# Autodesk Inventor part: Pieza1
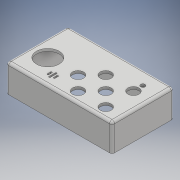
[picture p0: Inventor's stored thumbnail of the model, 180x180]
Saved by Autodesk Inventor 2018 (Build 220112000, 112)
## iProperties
Created: 2020-12
Part Number: Pieza1
Material: Genérico
Document SubType Name: Modeling
Designer: ULISES
Density: 1 g/cm^3
Appearance: Valor por defecto
Author: ULISES
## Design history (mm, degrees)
sketch "Boceto1"
  geometry: L1 (0, 0)-(80, 0); L2 (80, 0)-(80, 45); L3 (80, 45)-(0, 45); L4 (0, 45)-(0, 0); L5 (26, 9.5)-(26, 4.5); L6 (25.4, 9.5)-(25.4, 4.5); L7 (26.6, 4.5)-(26.6, 9.5); L8 (28.5, 8.25)-(28.5, 5.75); L9 (27.9, 8.25)-(27.9, 5.75); L10 (29.1, 5.75)-(29.1, 8.25); L11 (23.5, 8.25)-(23.5, 5.75); L12 (22.9, 5.75)-(22.9, 8.25); L13 (24.1, 8.25)-(24.1, 5.75); C1 r 4.4 at (69, 28); C2 r 4.4 at (69, 6); C3 r 4.4 at (58, 17); C4 r 4.4 at (47, 28); C5 r 4.4 at (47, 6); C6 r 4.4 at (36, 17); C7 r 9 at (12, 17); C8 r 4.4 at (26, 7); C9 r 1.75 at (69, 35.5); A1 r 0.6 centre (26, 9.5) between (26.6, 9.5) and (25.4, 9.5); A2 r 0.6 centre (26, 4.5) between (25.4, 4.5) and (26.6, 4.5); A3 r 0.6 centre (28.5, 8.25) between (29.1, 8.25) and (27.9, 8.25); A4 r 0.6 centre (28.5, 5.75) between (27.9, 5.75) and (29.1, 5.75); A5 r 0.6 centre (23.5, 8.25) between (24.1, 8.25) and (22.9, 8.25); A6 r 0.6 centre (23.5, 5.75) between (22.9, 5.75) and (24.1, 5.75); 3 further points
  constraints: 32 end point, 15 centre point, 12 point on circle, 8 tangent, 7 symmetric about line, 4 horizontal alignment, 4 parallel, 3 vertical alignment, 2 midpoint, 2 vertical, 1 coincident, 1 horizontal, 1 perpendicular, 2 other
  dimensions: "d0" = 7.5 distance of C1.centre C9.centre; "d1" = 22 distance of C2.centre C1.centre (= d2); "d2" = 22 distance of C1.centre C4.centre; "d3" = 11 horizontal distance of C4.centre C3.centre (= 0.5 x d2); "d4" = 11 horizontal distance of C6.centre C4.centre (= d3); "d5" = 11 horizontal distance of C4.centre C3.centre (= d3); "d6" = 24 distance of C6.centre C7.centre; "d7" = 10 horizontal distance of C6.centre C8.centre; "d8" = 10 horizontal distance of C8.centre C6.centre (= d7); "d9" = 17 distance from line of L3 C1.centre; "d10" = 6 distance from line of L1 C2.centre; "d12" = 33 distance from line of L2 C4.centre; "d13" = 12 distance from line of L4 C7.centre; "d14" = 3.5 diameter of C9; "d15" = 8.8 diameter of C1; "d16" = 8.8 diameter of C2; "d17" = 8.8 diameter of C3; "d18" = 8.8 diameter of C5; "d19" = 8.8 diameter of C4; "d20" = 8.8 diameter of C6; "d21" = 8.8 diameter of C8; "d22" = 5 distance of L5.start L5.end; "d23" = 0.6 distance between parallel lines of L7 L5; "d24" = 0.6 distance between parallel lines of L10 L8; "d25" = 2.5 distance between parallel lines of L5 L8; "d26" = 2.5 distance of L8.start L8.end (= 0.5 x d22); "d27" = 1.25 vertical distance of L5.end L8.end (= 0.5 x d26); "d28" = 18 diameter of C7
extrude "Extrusión1" new body sketch "Boceto1" distance "d29" = 2; taper "d30" = 0 deg
sketch "Boceto2"
  geometry: L1 (26.6, 9.5)-(26.6, 4.5) reference; L2 (25.4, 4.5)-(25.4, 9.5) reference; L3 (22.9, 5.75)-(22.9, 8.25) reference; L4 (24.1, 8.25)-(24.1, 5.75) reference; L5 (29.1, 8.25)-(29.1, 5.75) reference; L6 (27.9, 5.75)-(27.9, 8.25) reference; L7 (0, 0)-(80, 0) reference; L8 (80, 0)-(80, 45) reference; L9 (80, 45)-(0, 45) reference; L10 (0, 45)-(0, 0) reference; L11 (82, 47)-(82, -2); L12 (82, -2)-(-2, -2); L13 (-2, -2)-(-2, 47); L14 (-2, 47)-(82, 47); C1 r 9 at (12, 17) reference; C2 r 4.4 at (36, 17) reference; C3 r 4.4 at (47, 6) reference; C4 r 4.4 at (47, 28) reference; C5 r 4.4 at (58, 17) reference; C6 r 4.4 at (69, 6) reference; C7 r 4.4 at (69, 28) reference; C8 r 1.75 at (69, 35.5) reference; A1 r 0.6 centre (26, 9.5) between (26.6, 9.5) and (25.4, 9.5) reference; A2 r 0.6 centre (26, 4.5) between (25.4, 4.5) and (26.6, 4.5) reference; A3 r 0.6 centre (23.5, 5.75) between (22.9, 5.75) and (24.1, 5.75) reference; A4 r 0.6 centre (23.5, 8.25) between (24.1, 8.25) and (22.9, 8.25) reference; A5 r 0.6 centre (28.5, 8.25) between (29.1, 8.25) and (27.9, 8.25) reference; A6 r 0.6 centre (28.5, 5.75) between (27.9, 5.75) and (29.1, 5.75) reference; 1 further point
  constraints: 8 end point, 3 other
  dimensions: "d31" = 2 distance between parallel lines of L8 L11
extrude "Extrusión2" join sketch "Boceto2" distance "d32" = 22; taper "d33" = 0 deg
fillet "Empalme2" dims "d35" = 2
sketch "Boceto3"
  geometry: C1 r 4.4 at (-47, 28) reference; C2 r 4.4 at (-58, 17) reference; C3 r 4.4 at (-36, 17) reference; C4 r 4.4 at (-47, 6) reference; C5 r 3.5 at (-49.5, 14.5); C6 r 1.4 at (-49.5, 14.5); 1 further point
  constraints: 2 centre point, 1 coincident
  dimensions: "d36" = 2.5 horizontal distance of C4.centre C5.centre; "d37" = 2.5 vertical distance of C2.centre C5.centre; "d38" = 2.8 diameter of C6; "d39" = 7 diameter of C5
extrude "Extrusión3" join sketch "Boceto3" distance "d40" = 10; taper "d41" = 0 deg
fillet "Empalme3" dims "d42" = 2
sketch "Boceto5"
  geometry: L1 (0, 0)-(-80, 0) reference; L2 (0, 45)-(0, 0) reference; L3 (-80, 45)-(0, 45) reference; L4 (-80, 0)-(-80, 45) reference; L5 (-27.9, 8.25)-(-27.9, 5.75) reference; L6 (-29.1, 5.75)-(-29.1, 8.25) reference; L7 (-24.1, 5.75)-(-24.1, 8.25) reference; L8 (-22.9, 8.25)-(-22.9, 5.75) reference; L9 (-25.4, 9.5)-(-25.4, 4.5) reference; L10 (-26.6, 4.5)-(-26.6, 9.5) reference; L11 (-5, 45)-(0, 40); L12 (0, 45)-(-80, 45) reference; L13 (-5, 45)-(0, 45); L14 (0, 45)-(0, 40); L15 (0, 0)-(0, 45) reference; L16 (0, 22.5)-(-3.469, 22.5); L17 (-5, 0)-(0, 0); L18 (0, 0)-(0, 5); L19 (-5, 0)-(0, 5); L20 (-40, 45)-(-40, 40); L21 (-80, 0)-(-80, 5); L22 (-75, 0)-(-80, 0); L23 (-75, 0)-(-80, 5); L24 (-80, 45)-(-80, 0); L25 (-80, 0)-(-80, 45); L26 (-80, 0)-(0, 0); L27 (-80, 45)-(0, 45); L28 (0, 45)-(-80, 45); L29 (-75, 45)-(-80, 40); L30 (-80, 45)-(-80, 40); L31 (-75, 45)-(-80, 45); L32 (-80, 22.5)-(-76.531, 22.5); C1 r 1.75 at (-69, 35.5) reference; C2 r 4.4 at (-69, 28) reference; C3 r 4.4 at (-69, 6) reference; C4 r 4.4 at (-47, 28) reference; C5 r 4.4 at (-36, 17) reference; C6 r 9 at (-12, 17) reference; C7 r 9 at (-68, 17); A1 r 5.5 centre (-49.5, 14.5) between (-45.974, 10.279) and (-53.721, 18.026) reference; A2 r 4.4 centre (-47, 6) between (-50.179, 9.042) and (-45.974, 10.279) reference; A3 r 5.5 centre (-49.5, 14.5) between (-54.958, 13.821) and (-50.179, 9.042) reference; A4 r 4.4 centre (-58, 17) between (-53.721, 18.026) and (-54.958, 13.821) reference; A5 r 0.6 centre (-28.5, 8.25) between (-27.9, 8.25) and (-29.1, 8.25) reference; A6 r 0.6 centre (-28.5, 5.75) between (-29.1, 5.75) and (-27.9, 5.75) reference; A7 r 0.6 centre (-23.5, 5.75) between (-24.1, 5.75) and (-22.9, 5.75) reference; A8 r 0.6 centre (-23.5, 8.25) between (-22.9, 8.25) and (-24.1, 8.25) reference; A9 r 0.6 centre (-26, 9.5) between (-25.4, 9.5) and (-26.6, 9.5) reference; A10 r 0.6 centre (-26, 4.5) between (-26.6, 4.5) and (-25.4, 4.5) reference
  constraints: 40 end point, 14 symmetric about line, 4 point on line, 2 midpoint, 1 centre point, 1 collinear, 1 horizontal, 1 perpendicular, 1 vertical, 1 other
  dimensions: "d43" = 5 distance of L2.start L11.end; "d44" = 5 distance of L2.start L11.start
extrude "Extrusión4" join sketch "Boceto5" distance "d45" = 10; taper "d46" = 0 deg
node "Sólido1"
node "Contorno proyectado1"
node "Contorno proyectado8"
